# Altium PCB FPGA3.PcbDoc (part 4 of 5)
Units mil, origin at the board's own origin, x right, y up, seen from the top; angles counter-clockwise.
Board outline 4000 x 2750 mil, 12 copper layers (Top Layer, Plane1, MidLayer1, Plane2, MidLayer2, Plane3, Plane4, MidLayer 3, Plane5, MidLayer 4, Plane6, Bottom Layer), stack 57.29 mil thick; 420 components, 368 nets, 1889 pads, 1236 vias.
Unrouted connection lines stored in the file: 1.
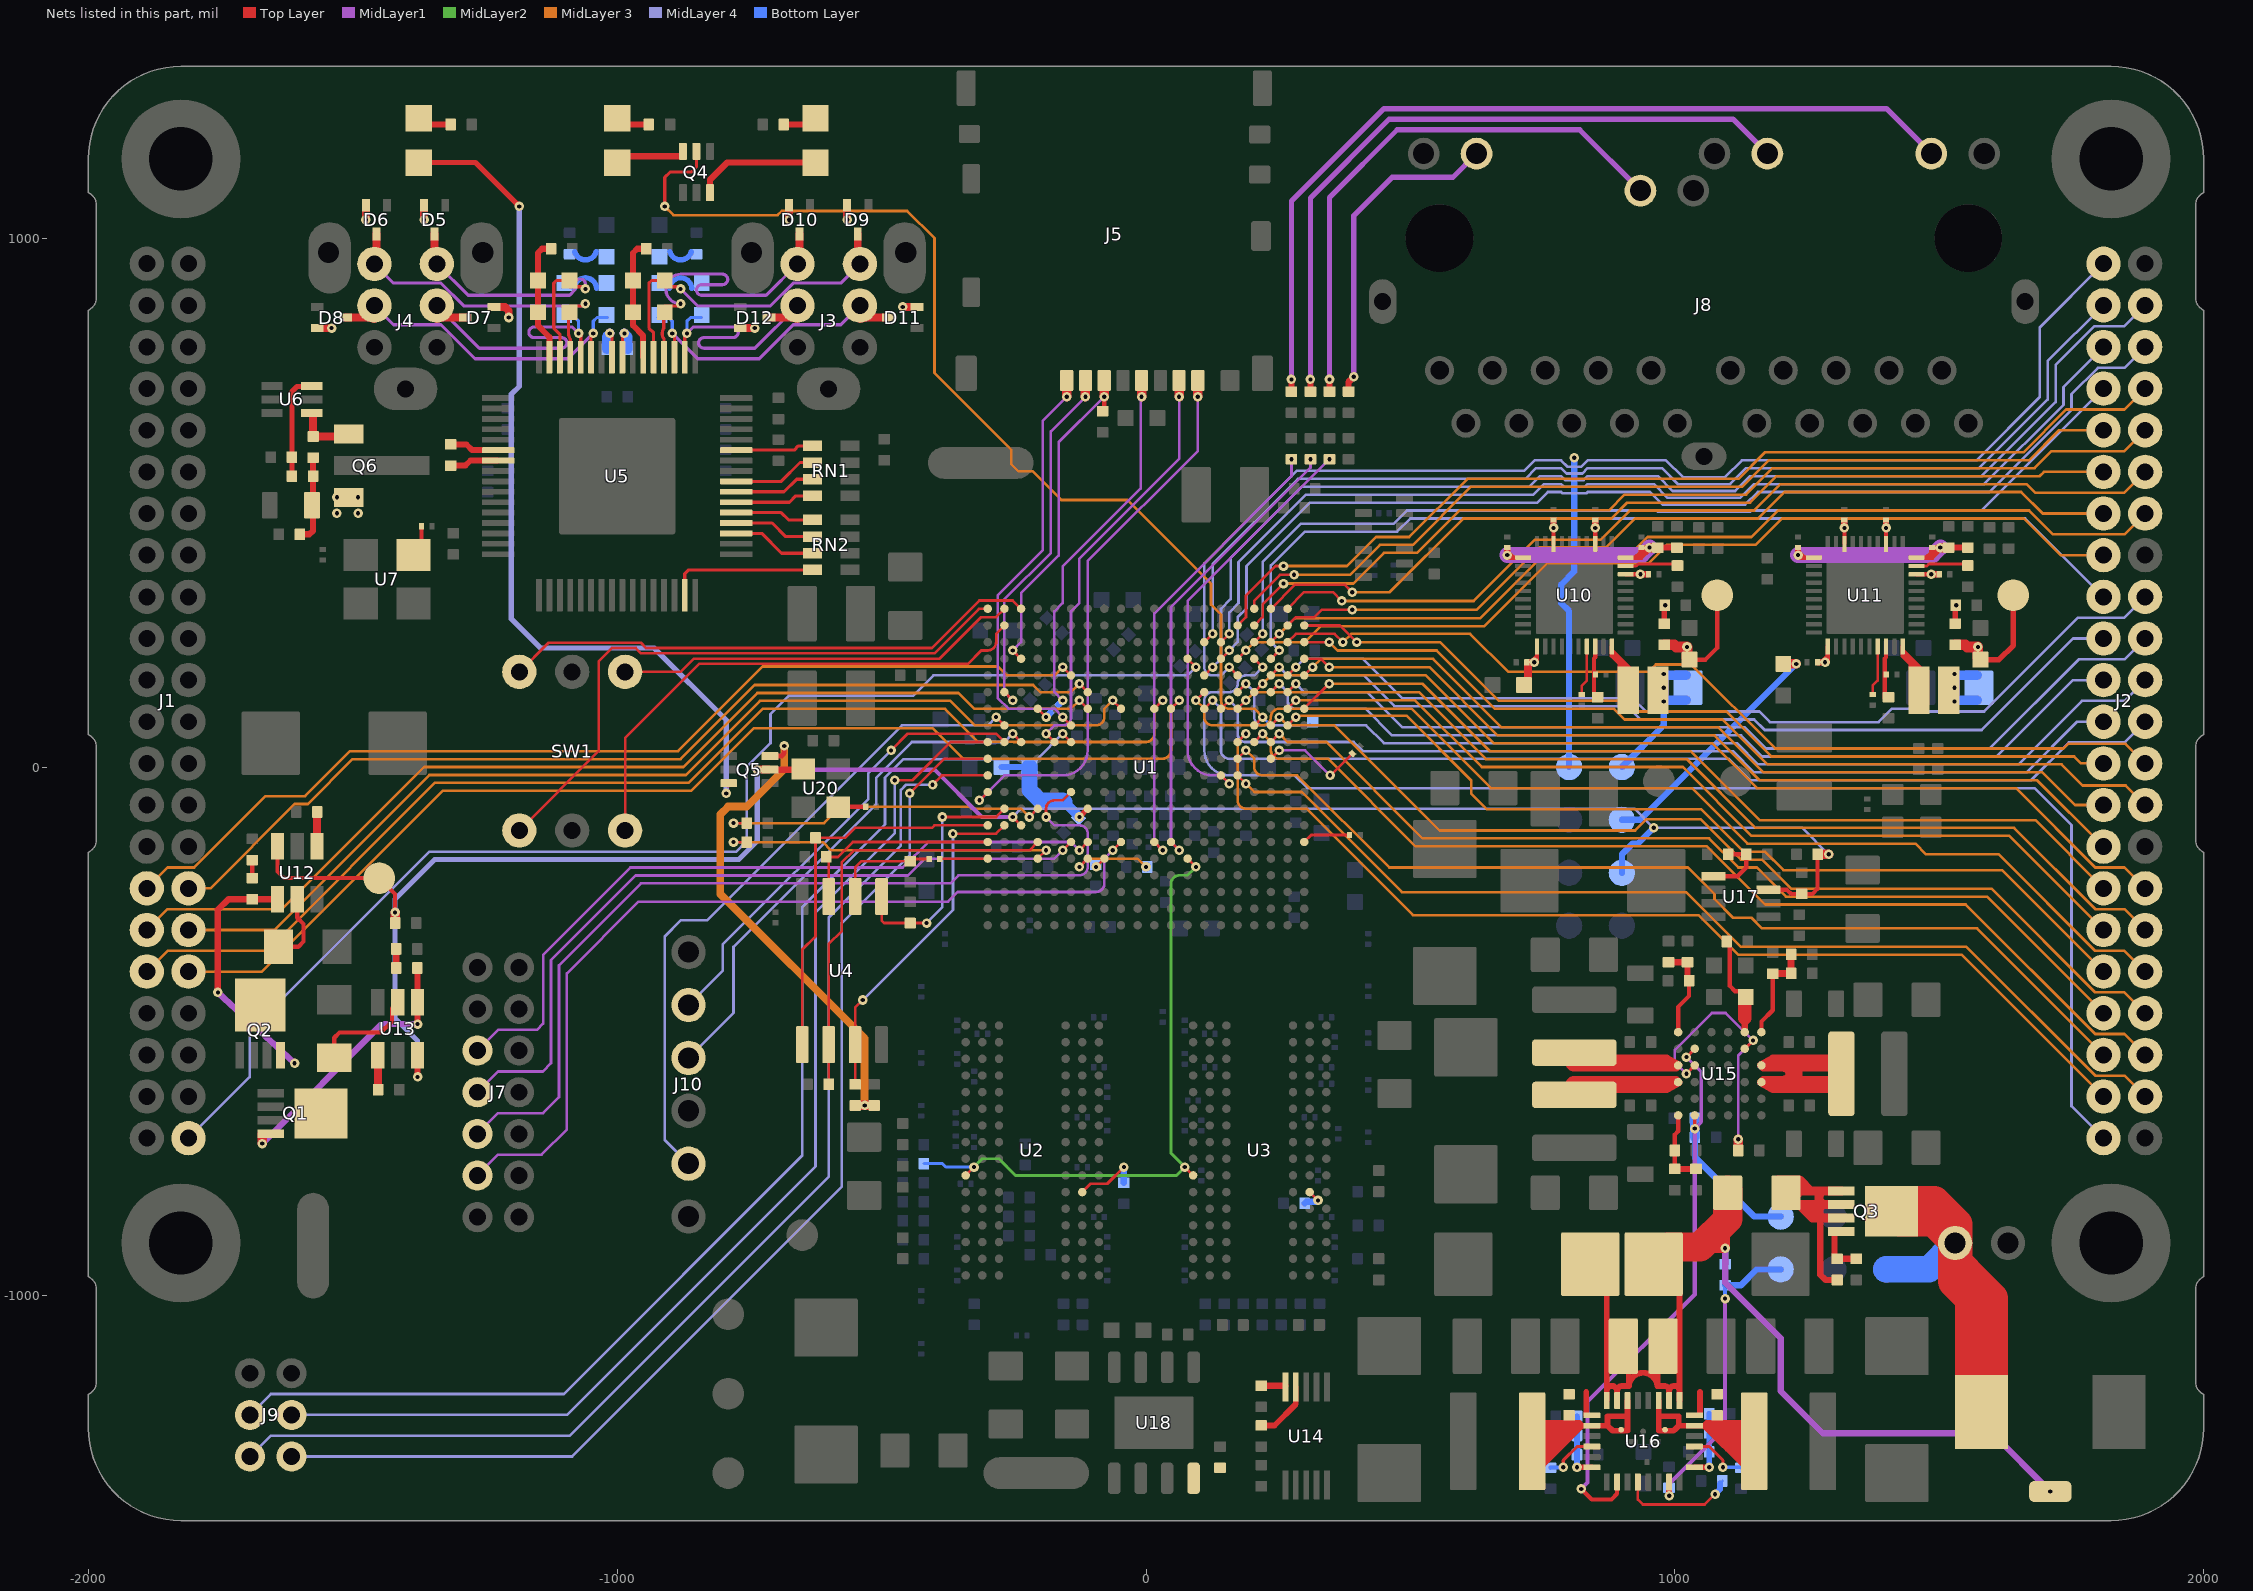
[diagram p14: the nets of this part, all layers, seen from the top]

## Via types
v1: diameter 18, hole 8, Top Layer to Bottom Layer, tented both sides, 1236 vias

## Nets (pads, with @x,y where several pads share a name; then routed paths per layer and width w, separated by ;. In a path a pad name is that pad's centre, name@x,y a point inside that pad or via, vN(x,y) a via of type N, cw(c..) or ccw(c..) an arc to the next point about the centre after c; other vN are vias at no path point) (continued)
IO1-27: J1.31 U1.G15 | length 1879.1
  Top Layer w5: v1(-125.98,157.48) U1.G15@-110.24,141.73
  MidLayer 3 w5: J1.31@-1809.96,-230 J1.31@-1810.63,-229.33 -1769.33,-229.33 -1610,-70 -1585,-70 -1500,15 -880,15 -740,155 -213.27,155 -200,141.73 -141.73,141.73 v1(-125.98,157.48)
IO1-28: J1.32 U1.F16 | length 1941.3
  Top Layer w5: v1(-157.48,188.98) U1.F16@-141.73,173.23
  MidLayer 3 w5: J1.32@-1889.37,-229.33 -1850,-189.96 -1799.96,-189.96 -1665,-55 -1590,-55 -1505,30 -885,30 -725,190 -280,190 -263.23,173.23 -173.23,173.23 v1(-157.48,188.98)
IO1-29: J1.33 U1.J14 | length 1999.7
  Top Layer w5: v1(-62.99,125.98) U1.J14@-47.24,110.24
  MidLayer 3 w5: J1.33@-1810.63,-308.07 -1648.07,-308.07 -1355,-15 -870,-15 -730,125 -370,125 -323.74,78.74 -94.33,78.74 ccw(c-94.49,94.49) -78.74,94.49 -78.74,110.24 v1(-62.99,125.98)
IO1-30: J1.34 U1.G14 | length 1990.1
  Top Layer w5: v1(-125.98,125.98) U1.G14@-110.24,110.24
  MidLayer 3 w5: J1.34@-1889.37,-308.07 -1850,-268.7 -1633.7,-268.7 -1365,0 -875,0 -735,140 -354.76,140 -325,110.24 -141.73,110.24 v1(-125.98,125.98)
IO1-31: J1.35 U1.M14 | length 2204.3
  Top Layer w5: U1.M14@47.24,110.24 v1(62.99,125.98)
  MidLayer 3 w5: J1.35@-1810.63,-386.81 -1671.81,-386.81 -1330,-45 -860,-45 -742,73 -403,73 -345.75,15.75 -265,15.75 31.66,15.75 ccw(c31.5,31.5) 47.24,31.5 47.24,110.24 v1(62.99,125.98)
IO1-32: J1.36 U1.L14 | length 2237.6
  Top Layer w5: U1.L14@15.75,110.24 v1(31.5,125.98)
  MidLayer 3 w5: J1.36@-1889.37,-386.81 -1850,-347.44 -1662.44,-347.44 -1345,-30 -865,-30 -725,110 -380,110 -317.49,47.49 -250,47.49 ; -250,47.24 0.16,47.24 ccw(c0,62.99) 15.75,62.99 15.75,110.24 v1(31.5,125.98)
IO1-33: J1.43 U1.N17 | length 2461.2
  Top Layer w5: U1.N17@78.74,204.72 v1(94.49,188.98)
  MidLayer 4 w5: J1.43@-1810.63,-701.77 -1695,-586.14 -1695,-500 -1355,-160 -774.67,-160 -755,-140.33 -755,0 -710,45 -710,100 -675,135 -440,135 -401.77,173.23 78.74,173.23 v1(94.49,188.98)
IO2-0: J2.2 U1.T16 | length 2330
  Top Layer w5: v1(157.48,188.98) U1.T16@173.23,173.23
  MidLayer 4 w5: v1(157.48,188.98) 141.73,173.23 125.98,173.23 cw(c125.98,188.98) 110.24,188.98 110.24,385.24 285,560 715,560 735,580 785,580 797.5,567.5 822.5,567.5 835,580 983,580 1015,548 1095,548 1127,580 1570,580 1690,700 1690,831.14 J2.2@1810.63,951.77
IO2-1: J2.3 U1.P16 | length 2240.2
  Top Layer w5: U1.P16@110.24,173.23 v1(125.98,188.98)
  MidLayer 4 w5: v1(125.98,188.98) 141.73,204.72 141.73,299.21 160,317.48 160,395 295,530 725,530 745,550 785,550 792.5,542.5 827.5,542.5 835,550 968,550 996,522 1114,522 1142,550 1580,550 1720,690 1720,760 1793.66,833.66 1850,833.66 J2.3@1889.37,873.03
IO2-2: J2.4 U1.P18 | length 2116.8
  Top Layer w5: U1.P18@110.24,236.22 v1(125.98,251.97)
  MidLayer 4 w5: v1(125.98,251.97) 125.98,383.48 287.5,545 717.5,545 737.5,565 785,565 795,555 825,555 835,565 975.5,565 1005.5,535 1104.5,535 1134.5,565 1575,565 1705,695 1705,767.4 J2.4@1810.63,873.03
IO2-3: J2.5 U1.R17 | length 2105.8
  Top Layer w5: U1.R17@141.73,204.72 v1(157.48,220.47)
  MidLayer 4 w5: v1(157.48,220.47) 173.23,236.22 173.23,283.23 190,300 190,380 310,500 740,500 760,520 785,520 787.5,517.5 832.5,517.5 835,520 953,520 977,496 1133,496 1157,520 1595,520 1750,675 1750,705 1799.92,754.92 1850,754.92 J2.5@1889.37,794.29
IO2-4: J2.6 U1.R18 | length 2025.9
  Top Layer w5: U1.R18@141.73,236.22 v1(157.48,251.97)
  MidLayer 4 w5: v1(157.48,251.97) 157.48,292.48 175,310 175,387.5 302.5,515 732.5,515 752.5,535 785,535 790,530 830,530 835,535 960.5,535 986.5,509 1123.5,509 1149.5,535 1585,535 1735,685 1735,718.66 J2.6@1810.63,794.29 J2.6@1799.29,794.29
IO2-5: J2.7 U1.T19 | length 1925.4
  Top Layer w5: U1.T19@173.23,267.72 188.98,283.46 188.98,323.98 245,380 v1(260,380)
  MidLayer 3 w5: v1(260,380) 380,380 435,435 497.5,435 607.5,545 1120,545 1170,595 1658.82,595 1740,676.18 1850,676.18 J2.7@1889.37,715.55
IO2-6: J2.8 U1.U18 | length 1885.8
  Top Layer w5: U1.U18@204.72,236.22 v1(220.47,251.97)
  MidLayer 4 w5: v1(220.47,251.97) 220.47,387.97 292.5,460 468.33,460 493.33,485 965.5,485 967.5,483 1142.5,483 1144.5,485 1580.08,485 J2.8@1810.63,715.55
IO2-7: J2.9 U1.U19 | length 1851.6
  Top Layer w5: U1.U19@204.72,267.72 220.47,283.46 220.47,307.47 v1(260,347)
  MidLayer 3 w5: v1(260,347) 392,347 450,405 512.5,405 593,485.5 875.5,485.5 905,515 1135,515 1185,565 1680,565 1712.44,597.44 1850,597.44 J2.9@1889.37,636.81
IO2-8: J2.10 U1.U20 | length 1757.2
  Top Layer w5: U1.U20@204.72,299.21 204.72,314.72 253.5,363.5 v1(280,363.5)
  MidLayer 3 w5: v1(280,363.5) 386,363.5 442.5,420 505,420 615,530 1127.5,530 1177.5,580 1670,580 1726.81,636.81 J2.10@1810.63,636.81 J2.10@1808.95,635.13
IO2-9: J2.11 U1.W20 | length 1756.2
  Top Layer w5: U1.W20@267.72,299.21 299.16,330.66 353.34,330.66 v1(370,314)
  MidLayer 3 w5: v1(370,314) 619.5,314 735.5,430 860,430 915,485 1150,485 1200,535 1665,535 1681.3,518.7 1850,518.7 J2.11@1889.37,558.07
IO2-10: J2.12 U1.V20 | length 1693.6
  Top Layer w5: U1.V20@236.22,299.21 282.01,345 375.5,345 v1(390,330.5)
  MidLayer 3 w5: v1(390,330.5) 460.5,330.5 600,470 880,470 910,500 1142.5,500 1192.5,550 1690,550 1698.07,558.07 J2.12@1810.63,558.07
IO2-11: J2.13 U1.V18 | length 1791.2
  Top Layer w5: U1.V18@236.22,236.22 v1(251.97,251.97)
  MidLayer 3 w5: v1(251.97,251.97) 281,281 631.5,281 750.5,400 913.67,400 948.67,435 1145,435 1195,485 1670,485 1715.04,439.96 1850,439.96 J2.13@1889.37,479.33
IO2-12: J2.14 U1.W19 | length 1664.3
  Top Layer w5: U1.W19@267.72,267.72 283.46,283.46 318.46,283.46 332.5,297.5 v1(390,297.5)
  MidLayer 3 w5: v1(390,297.5) 625.5,297.5 743,415 870,415 925,470 1157.5,470 1207.5,520 1655,520 1695.67,479.33 J2.14@1810.63,479.33
IO2-13: J2.16 U1.T17 | length 1776
  Top Layer w5: U1.T17@173.23,204.72 v1(188.98,220.47)
  MidLayer 3 w5: v1(188.98,220.47) 204.72,236.22 300.24,236.22 330.02,266 639,266 758,385 950,385 985,420 1152.5,420 1202.5,470 1660,470 1729.41,400.59 J2.16@1810.63,400.59
IO2-14: J2.17 U1.W16 | length 1786.5
  Top Layer w5: U1.W16@267.72,173.23 v1(283.46,188.98)
  MidLayer 4 w5: v1(283.46,188.98) 299.21,204.72 410.28,204.72 485,130 920,130 945,105 1160,105 1180,85 1385,85 1410,110 1450,110 1455,105 1585,105 1762.48,282.48 1850,282.48 J2.17@1889.37,321.85
IO2-15: J2.18 U1.V17 | length 1862
  Top Layer w5: U1.V17@236.22,204.72 v1(251.97,220.47)
  MidLayer 4 w5: v1(251.97,220.47) 236.22,236.22 236.22,380.99 300.23,445 475,445 500,470 1662.48,470 J2.18@1810.63,321.85
IO2-16: J2.19 U1.W15 | length 1765.1
  Top Layer w5: U1.W15@267.72,141.73 v1(283.46,157.48)
  MidLayer 4 w5: v1(283.46,157.48) 299.21,141.73 418.27,141.73 485,75 1132.5,75 1172.5,35 1595,35 1763.74,203.74 1850,203.74 J2.19@1889.37,243.11
IO2-17: J2.20 U1.V16 | length 1701.9
  Top Layer w5: U1.V16@236.22,173.23 v1(251.97,188.98)
  MidLayer 4 w5: v1(251.97,188.98) 267.72,173.23 411.77,173.23 470,115 910,115 935,90 1150,90 1170,70 1580,70 1753.11,243.11 J2.20@1810.63,243.11
IO2-18: J2.21 U1.T15 | length 1882
  Top Layer w5: U1.T15@173.23,141.73 v1(188.98,157.48)
  MidLayer 4 w5: v1(188.98,157.48) 204.72,141.73 204.72,94.49 ccw(c220.47,94.49) 220.47,78.74 416.26,78.74 450,45 1117.5,45 1157.5,5 1650,5 1770,125 1850,125 J2.21@1889.37,164.37
IO2-19: J2.22 U1.V15 | length 1709.4
  Top Layer w5: U1.V15@236.22,141.73 v1(251.97,157.48)
  MidLayer 4 w5: v1(251.97,157.48) 267.72,141.73 267.72,125.98 ccw(c283.46,125.98) 283.46,110.24 414.76,110.24 465,60 1125,60 1165,20 1608.13,20 1752.5,164.37 J2.22@1810.63,164.37
IO2-20: J2.23 U1.P14 | length 2024.9
  Top Layer w5: U1.P14@110.24,110.24 v1(125.98,125.98)
  MidLayer 4 w5: 141.73,50.17 141.73,110.24 ; J2.23@1889.37,85.63 1850,46.26 1745,46.26 1673.74,-25 1142.5,-25 1101.75,15.75 157.48,15.75 cw(c157.48,31.5) 141.73,31.5 141.73,110.24 ; 141.73,110.24 v1(125.98,125.98) 141.73,110.24
IO2-21: J2.24 U1.R14 | length 1801.5
  Top Layer w5: U1.R14@141.73,110.24 v1(157.48,125.98)
  MidLayer 4 w5: v1(157.48,125.98) 173.23,110.24 173.23,62.99 ccw(c188.98,62.99) 188.98,47.24 392.76,47.24 410,30 1110,30 1150,-10 1665,-10 1760.63,85.63 J2.24@1810.63,85.63
IO2-22: J2.25 U1.W18 | length 1761.6
  Top Layer w5: U1.W18@267.72,236.22 283.46,251.97 356.71,251.97 v1(372.46,236.22)
  MidLayer 3 w5: v1(372.46,236.22) 388.2,251.97 613.03,251.97 685,180 950,180 964,194 1031,194 1190,35 1735,35 1743.78,43.78 1852.48,43.78 J2.25@1889.37,6.89
IO2-23: J2.26 U1.Y19 | length 1623.7
  Top Layer w5: U1.Y19@299.21,267.72 366.96,267.72 v1(398.46,236.22)
  MidLayer 3 w5: v1@394.21,236.22 v1(398.46,236.22) 556.28,236.22 667.5,125 895,125 915,105 1097.5,105 1182.5,20 1755,20 1768.11,6.89 J2.26@1810.63,6.89
IO2-24: J2.27 U1.Y18 | length 1713.5
  Top Layer w5: U1.Y18@299.21,236.22 v1@342.21,236.22
  MidLayer 3 w5: v1(346.46,236.22) 362.2,220.47 549.53,220.47 660,110 885,110 905,90 1090,90 1175,5 1731.3,5 1771.26,-34.96 1852.48,-34.96 J2.27@1889.37,-71.85
IO2-25: J2.28 U1.Y16 | length 1644.9
  Top Layer w5: U1.Y16@299.21,173.23 v1(314.96,188.98)
  Top Layer w6: J2.28@1806.48,-76 J2.28@1810.63,-71.85
  MidLayer 3 w5: v1(314.96,188.98) 330.71,204.72 542.78,204.72 672.5,75 1082.5,75 1167.5,-10 1695,-10 1756.85,-71.85 J2.28@1810.63,-71.85
IO2-26: J2.30 U1.Y17 | length 1658.6
  Top Layer w5: U1.Y17@299.21,204.72 330.71,204.72 v1(346.46,188.98)
  MidLayer 3 w5: v1(346.46,188.98) 536.02,188.98 665,60 1075,60 1160,-25 1685.04,-25 J2.30@1810.63,-150.59
IO2-27: J2.31 U1.U15 | length 1864.4
  Top Layer w5: U1.U15@204.72,141.73 v1(220.47,157.48)
  MidLayer 3 w5: v1(220.47,157.48) 236.22,173.23 529.27,173.23 657.5,45 1070,45 1155,-40 1645,-40 1794.96,-189.96 1850,-189.96 J2.31@1889.37,-229.33
IO2-28: J2.32 U1.Y14 | length 1691.2
  Top Layer w5: U1.Y14@299.21,110.24 v1(346.46,157.48)
  MidLayer 3 w5: v1(346.46,157.48) 522.52,157.48 650,30 1030,30 1160.5,-100.5 1681.8,-100.5 J2.32@1810.63,-229.33
IO2-29: J2.33 U1.T14 | length 1915.5
  Top Layer w5: U1.T14@173.23,110.24 v1(188.98,125.98)
  MidLayer 3 w5: v1(188.98,125.98) 204.72,141.73 515.77,141.73 642.5,15 1022.5,15 1152.5,-115 1641.26,-115 1794.96,-268.7 1850,-268.7 J2.33@1889.37,-308.07
IO2-30: J2.34 U1.W14 | length 1729.2
  Top Layer w5: U1.W14@267.72,110.24 v1(283.46,125.98)
  MidLayer 3 w5: v1(283.46,125.98) 509.02,125.98 635,0 1015,0 1145,-130 1632.56,-130 J2.34@1810.63,-308.07
IO2-31: J2.35 U1.P15 | length 2072.3
  Top Layer w5: v1(94.49,125.98) U1.P15@110.24,141.73
  MidLayer 3 w5: v1(94.49,125.98) 110.24,110.23 110.24,94.49 ccw(c125.98,94.49) 125.98,78.74 220.47,78.74 ccw(c220.47,94.49) 236.22,94.49 cw(c251.97,94.49) 251.97,110.24 502.26,110.24 652.5,-40 1032.5,-40 1137.5,-145 1455,-145 1475,-165 1612.52,-165 1794.96,-347.44 1850,-347.44 J2.35@1889.37,-386.81
IO2-32: J2.36 U1.W13 | length 1765.5
  Top Layer w5: U1.W13@267.72,78.74 v1(283.46,94.49)
  MidLayer 3 w5: v1(283.46,94.49) 285.95,96.98 292.87,96.98 ; 292.89,97 493,97 615,-25 615,-50 645,-80 1050,-80 1130,-160 1170,-160 1205,-195 1618.82,-195 J2.36@1810.63,-386.81
IO2-33: J2.37 U1.V13 | length 1909.5
  Top Layer w5: U1.V13@236.22,78.74 v1(251.97,94.49)
  MidLayer 3 w5: v1(251.97,94.49) 267.72,78.74 356.26,78.74 555,-120 925,-120 946.5,-98.5 1048.5,-98.5 1125,-175 1165,-175 1220,-230 1598.78,-230 1794.96,-426.18 1850,-426.18 J2.37@1889.37,-465.55
IO2-34: J2.38 U1.V12 | length 1799.9
  Top Layer w5: U1.V12@236.22,47.24 v1(251.97,62.99)
  MidLayer 3 w5: v1(251.97,62.99) 267.72,47.24 340.92,47.24 523.17,-135 1065,-135 1120,-190 1155,-190 1210,-245 1590.08,-245 J2.38@1810.63,-465.55
IO2-35: J2.39 U1.U12 | length 1954.6
  Top Layer w5: U1.U12@204.72,47.24 v1(220.47,62.99)
  MidLayer 3 w5: v1(220.47,62.99) 236.22,47.24 236.22,31.34 ; 236.22,31.5 ccw(c251.97,31.5) 236.22,31.34 ; J2.39@1889.37,-544.29 1850,-504.92 1794.96,-504.92 1550.04,-260 1170.54,-260 1060.54,-150 510,-150 344.25,15.75 251.97,15.75 cw(c251.97,31.5) 236.22,31.34
IO2-36: J2.40 U1.T11 | length 1900
  Top Layer w5: U1.T11@173.23,15.75 v1(188.98,31.5)
  MidLayer 3 w5: v1(188.98,31.5) 204.73,15.75 204.73,-0.16 ccw(c220.47,0) 220.47,-15.75 251.97,-15.75 285.75,-15.75 460,-190 1025,-190 1075,-240 1075,-250 1110,-285 1145,-285 1165,-305 1571.34,-305 J2.40@1810.63,-544.29
IO2-37: J2.41 U1.T10 | length 1967.7
  Top Layer w5: U1.T10@173.23,-15.75 v1(188.98,-31.5)
  MidLayer 3 w5: v1(188.98,-31.5) 204.73,-47.24 251.97,-47.24 294.74,-47.24 484,-236.5 1021.5,-236.5 1125,-340 1551.3,-340 1794.96,-583.66 1850,-583.66 J2.41@1889.37,-623.03
IO2-38: J2.42 U1.T12 | length 2026.6
  Top Layer w5: U1.T12@173.23,47.24 v1(188.98,62.99)
  MidLayer 3 w5: v1(188.98,62.99) 173.23,47.24 173.23,-63.15 ccw(c188.98,-62.99) 188.98,-78.74 251.97,-78.74 303.74,-78.74 505,-280 1045,-280 1120,-355 1542.6,-355 J2.42@1810.63,-623.03
IO2-39: J2.44 U1.U17 | length 2583.1
  Top Layer w5: U1.U17@204.72,204.72 v1(220.47,188.98)
  MidLayer 4 w5: v1(220.47,188.98) 204.72,173.23 188.98,173.23 ccw(c188.98,157.48) 173.23,157.48 cw(c157.48,157.48) 157.48,141.73 125.98,141.73 ccw(c125.98,125.98) 110.24,125.98 110.24,31.5 ccw(c157.48,31.5) 157.48,-15.75 280.75,-15.75 305,-40 1680,-40 1750,-110 1750,-641.14 J2.44@1810.63,-701.77
MIO6_8: R6.1 U1.A5 | length 91.1
  Top Layer w5: R6.1@-390,-174 -389.23,-173.23 U1.A5@-299.21,-173.23
MIO7_8: R84.2 U1.D8 | length 627.7
  Top Layer w5: v1(-780,-106) R84.2@-755,-106 ; v1(-220.47,-94.49) U1.D8@-204.72,-78.74
  MidLayer 3 w5: v1(-780,-106) -609,-106 -578,-75 -333.74,-75 -330,-78.74 -236.22,-78.74 v1(-220.47,-94.49)
MIO8_8: R85.2 U1.D5 | length 644.7
  Top Layer w5: v1(-780,-142) R85.2@-755,-142 ; U1.D5@-204.72,-173.23 v1(-188.98,-157.48)
  MidLayer 3 w5: v1(-780,-142) -610.97,-142 -595.48,-157.48 -531.17,-157.48 v1(-188.98,-157.48)
MIO34: J9.3 U1.A12 | length 2183.2
  Top Layer w5: v1(-475,-25) -441.68,-25 -369.44,47.24 U1.A12@-299.21,47.24
  MidLayer 4 w5: J9.3@-1615.63,-1225 -1095,-1225 -625,-755 -625,-275 -475,-125 v1(-475,-25)
MIO35: J9.4 U1.F12 | length 2419.7
  Top Layer w5: v1(-157.48,62.99) U1.F12@-141.73,47.24
  MidLayer 4 w5: J9.4@-1694.37,-1225 -1655,-1185.63 -1100.63,-1185.63 -650,-735 -650,-265 -493.5,-108.5 -493.5,-20.17 -458.34,15 -205.48,15 v1(-157.48,62.99)
MIO36: J9.5 U1.A11 | length 2223.5
  Top Layer w5: v1(-447,-50) -381.25,15.75 U1.A11@-299.21,15.75
  MidLayer 4 w5: J9.5@-1615.63,-1303.74 -1085.24,-1303.74 -575,-793.5 -575,-295 -447,-167 v1(-447,-50)
MIO37: J9.6 U1.A10 | length 2277.4
  Top Layer w5: v1(-403.5,-33.5) -385.75,-15.75 U1.A10@-299.21,-15.75
  MidLayer 4 w5: J9.6@-1694.37,-1303.74 -1655,-1264.37 -1089.37,-1264.37 -600,-775 -600,-285 -463.5,-148.5 -463.5,-43.17 -453.83,-33.5 v1(-403.5,-33.5)
NetC1_2: C1.2 R99.1 R108.2 U15.A1 | length 178.1
  Top Layer w8: U15.A1@1006.26,-501.26 1006.26,-453.74 1027,-433 R99.1@1027,-404
  Top Layer w12: C1.2@988,-369 R108.2@1024,-369 1024,-401 R99.1@1027,-404
NetC2_2: C2.2 R100.2 R106.1 U15.A6 | length 190.3
  Top Layer w8: U15.A6@1163.74,-501.26 1163.74,-481.26 1185,-460 R106.1@1185,-391
  Top Layer w13: R106.1@1185,-391 1185.85,-390.15 C2.2@1219.88,-390.15 R100.2@1219.88,-354.15
NetC3_2: C3.2 R101.1 R107.2 U15.F1 | length 137.6
  Top Layer w8: C3.2@1000,-753.74 R101.1@1000,-725 1000,-695 1006.26,-688.74 U15.F1@1006.26,-658.74
  Top Layer w12: C3.2@1000,-760 R107.2@1040,-760
NetC4_2: C4.2 R81.1 R103.2 U16.9 | length 129.2
  Top Layer w11: U16.9@1037,-1324.21 v1(1065,-1324.21)
  Bottom Layer w11: v1(1065,-1324.21) R103.2@1065,-1259 C4.2@1065,-1223
NetC5_2: C5.2 R97.1 R104.2 U16.28 | length 124.2
  Top Layer w11: v1(815,-1324.21) U16.28@843,-1324.21
  Bottom Layer w11: v1(815,-1324.21) C5.2@815,-1228
NetC6_1: C6.1 R76.1 R113.2 R114.2 | length 118.8
  Bottom Layer w10: -900.95,905.46 cw(c-880,904) -859.05,905.46 ; -900.38,974.92 ccw(c-880,980) R76.1@-859.62,974.92
NetC7_1: C7.1 R77.1 R115.2 R116.2 | length 118.8
  Bottom Layer w10: -1080.95,905.46 cw(c-1060,904) -1039.05,905.46 ; R77.1@-1080.38,974.92 ccw(c-1060,980) -1039.62,974.92
NetC8_1: C8.1 R36.2 | length 34
  Top Layer w8: R36.2@-1690,-210 C8.1@-1690,-176
NetC9_1: C9.1 R37.2 | length 36
  Top Layer w12: R37.2@-1418,-380 C9.1@-1418,-344
NetC10_1: C10.1 U5.54 | length 94.5
  Top Layer w11: C10.1@-1315,610 -1285,610 -1274.21,599.21 U5.54@-1225,599.21
NetC10_2: C10.2 U5.55 | length 92.9
  Top Layer w11: C10.2@-1315,570 -1287,570 -1277.47,579.53 U5.55@-1226,579.53
NetC21_1: C21.1 U18.4
NetC23_1: C23.1 U16.23 | length 44.3
  Top Layer w11: U16.23@832.5,-1225.79 832.5,-1181.5
NetC23_2: C23.2 L2.1 U16.20 U16.24 U16.33 | length 708.7
  Top Layer w11: L2.1@724.97,-1289.56 780.44,-1289.56 ; L2.1@734.97,-1279.56 790.44,-1279.56 ; L2.1@744.97,-1269.56 800.44,-1269.56 ; L2.1@750.3,-1319.69 820.5,-1249.5 ; 755,-1259.53 810.47,-1259.53 ; 800,-1249.5 820.5,-1249.5 ; 800,-1245 800.47,-1245.47 824.53,-1245.47 ; 800,-1240.5 819.56,-1240.5 824.53,-1245.47 ; 910.47,-1227.53 872.53,-1227.53 872.53,-1245.47 ; 910.47,-1220 U16.20@910.47,-1198 910.47,-1255.19 882.38,-1255.19 872.53,-1245.47 ; 820.5,-1249.5 824.53,-1245.47 ; 824.53,-1245.47 U16.24@843,-1245.47 872.53,-1245.47
  Top Layer w20: L2.1@735,-1245 800,-1245 ; L2.1@740.44,-1299.56 760.44,-1299.56
NetC24_1: C24.1 U16.14 | length 44.3
  Top Layer w11: U16.14@1047.5,-1225.79 1047.5,-1181.5
NetC24_2: C24.2 L1.1 U16.13 U16.17 U16.34 | length 686
  Top Layer w11: U16.17@969.53,-1198 969.53,-1227.53 ; 1069.53,-1259.53 L1.1@1125,-1259.53 ; 1079.56,-1269.56 L1.1@1135.03,-1269.56 ; 1079.53,-1245.47 1059.5,-1245.47 1055.47,-1245.47 ; 1080,-1249.5 1059.5,-1249.5 ; 1080,-1240.5 1060.44,-1240.5 1055.47,-1245.47 ; 1089.56,-1279.56 L1.1@1145.03,-1279.56 ; 1099.56,-1289.56 L1.1@1155.03,-1289.56 ; L1.1@1129.7,-1319.69 1059.5,-1249.5 ; 969.53,-1227.53 1007.47,-1227.53 1007.47,-1245.47 ; 969.53,-1227.53 969.53,-1255.19 981.5,-1255.19 997.62,-1255.19 1000.73,-1252.12 1007.47,-1245.47 ; 1007.47,-1245.47 U16.13@1037,-1245.47 1055.47,-1245.47 ; 1055.47,-1245.47 1059.5,-1249.5
  Top Layer w20: 1080,-1245 L1.1@1145,-1245 ; 1119.56,-1299.56 L1.1@1139.56,-1299.56
NetC31_1: C31.1 R109.1 R110.1 U5.47 | length 234.4
  Top Layer w11.5: U5.47@-1127.95,775 -1127.95,812.95 -1150,835 R110.1@-1150,860 R109.1@-1150,920 -1150,972 -1142,980 C31.1@-1125,980
NetC32_1: C32.1 R111.1 R112.1 U5.38 | length 233.3
  Top Layer w11.5: U5.38@-950.79,775 -950.79,815.79 -970,835 R112.1@-970,860 R111.1@-970,920 -970,972 -962,980 C32.1@-945,980
NetC33_1: C33.1 U12.1 | length 66
  Top Layer w8: C33.1@-1567.5,-87.5 C33.1@-1565,-85
  Top Layer w15: U12.1@-1567.5,-150 C33.1@-1567.5,-87.5
NetC34_1: C34.1 U13.1 | length 65.2
  Top Layer w15: U13.1@-1452.5,-545 -1452,-545.5 C34.1@-1452,-610
NetC35_1: C35.1 CB55.1 CB59.1 L13.1 U10.11 U10.40 | length 514.2
  Top Layer w8: v1@683,395.87 695.07,395.87 ; v1@686.54,404.4 695.07,395.87 ; U10.11@713,395.87 695.07,395.87 ; U10.40@907,395.87 937,395.87 951.52,410.39 963.39,410.39 C35.1@968,415 ; 924.93,395.87 935,405.94 935,414 936,415 CB55.1@937,415 ; 929,395.87 943.52,410.39
  Top Layer w10: CB55.1@938,415 v1(952,415)
  Top Layer w12: v1(683,400.87) 683,414 CB59.1@683,410 ; C35.1@968,415 L13.1@1004,415
  Top Layer w18: v1(952,415) C35.1@968,415
  MidLayer1 w30: v1(683,400.87) 937.87,400.87 v1(952,415)
NetC36_1: C36.1 CB53.1 CB57.1 CB61.1 L11.2 U10.3 U10.8 U10.38 | length 165.8
  Top Layer w8: U10.8@770.67,421.14 v1@770.67,451.14 ; U10.3@849.41,421.14 v1@849.41,451.14 ; U10.38@907,364.37 v1(935,364.37)
  Top Layer w10: L11.2@980,271 980,304 v1(982,306)
  Top Layer w12: v1(770.63,452) CB57.1@770.63,466 ; v1(849.37,452) CB61.1@849.37,466 ; v1(935,364.37) CB53.1@949,364.37
NetC37_1: C37.1 CB49.1 U10.28 | length 98.9
  Top Layer w8: C37.1@847.12,130 847.12,205.46 849.37,207.71 U10.28@849.37,228
NetC38_1: C38.1 CB56.1 CB60.1 L14.1 U11.11 U11.40 | length 510.2
  Top Layer w8: v1@1233,395.87 1245.07,395.87 ; v1@1236.54,404.4 1245.07,395.87 ; U11.11@1263,395.87 1245.07,395.87 ; U11.40@1457,395.87 1474.93,395.87 ; CB60.1@1487,415 1486,415 1485,414 1485,405.94 1474.93,395.87 ; 1493.52,410.39 1479,395.87 ; C38.1@1518,415 1513.39,410.39 1501.52,410.39 1487,395.87 1479,395.87 ; 1474.93,395.87 1479,395.87
  Top Layer w10: CB60.1@1488,415 v1(1502,415)
  Top Layer w12: v1(1233,400.87) CB56.1@1233,414 ; C38.1@1518,415 L14.1@1554,415
  Top Layer w18: v1(1502,415) C38.1@1518,415
  MidLayer1 w30: v1(1233,400.87) 1487.87,400.87 v1(1502,415)
NetC39_1: C39.1 CB54.1 CB58.1 CB62.1 L12.2 U11.3 U11.8 U11.38 | length 166.7
  Top Layer w8: U11.8@1320.63,422 v1(1320.63,452) ; U11.3@1399.37,422 v1(1399.37,452) ; U11.38@1457,364.37 v1(1485,364.37) ; CB54.1@1499.37,364.37 CB54.1@1500,365
  Top Layer w10: L12.2@1530,271 1530,304 v1(1532,306)
  Top Layer w12: v1(1320.63,452) CB58.1@1320.63,466 ; v1(1399.37,452) CB62.1@1399.37,466 ; v1(1485,364.37) CB54.1@1499,364.37
NetC40_1: C40.1 CB50.1 U11.28 | length 98.9
  Top Layer w8: C40.1@1397.12,130 1397.12,205.46 1399.37,207.71 U11.28@1399.37,228
NetC57_1: C57.1 CB52.1 CB134.1 CB136.1 L7.2 L12.1 pad.0@1640,325 TP9.1 U11.21 | length 898.3
  Top Layer w8: v1@1280.6,201.54 1289.13,210.07 ; v1@1289.13,198 1289.13,210.07 ; U11.21@1289.13,228 1289.13,210.07
  Top Layer w10: CB134.1@1578,203 1613,203 1640,230 pad.0@1640,325
  Top Layer w12: CB52.1@1271,198 v1(1284.13,198)
  Top Layer w18: CB136.1@1210,195 v1(1229.5,195)
  Top Layer w20: L12.1@1530,231 1549,231 1553,227 v1(1573,227) CB134.1@1573,207
  Bottom Layer w12: TP9.1@900,-100 934.5,-100 v1(1229.5,195)
  Bottom Layer w18: C57.1@1571.5,126.5 1531.5,126.5 v1(1529,124) v1(1529,150) v1(1529,176) 1531.5,173.5 C57.1@1571.5,173.5
NetC58_1: C58.1 CB51.1 CB135.1 CB140.1 L6.2 L11.1 pad.0@1080,325 TP7.1 U10.21 | length 643.5
  Top Layer w8: v1@730.6,201.54 739.13,210.07 ; v1@739.13,198 739.13,210.07 ; U10.21@739.13,228 739.13,210.07 ; CB135.1@1027,203 CB135.1@1028,203 1058,203 1080,225 pad.0@1080,325 pad.0@1080,340
  Top Layer w12: CB140.1@715,155 CB140.1@720,160 ; CB51.1@721,198 v1(734.13,198)
  Top Layer w15: CB140.1@722.5,158 CB51.1@722.5,196
  Top Layer w20: L11.1@980,231 999,231 1003,227 v1(1023,227) 1023,207 CB135.1@1027,203
  Bottom Layer w12: TP7.1@900,0 979,79 v1(979,124)
  Bottom Layer w18: C58.1@1021.5,126.5 981.5,126.5 v1(979,124) v1(979,150) v1(979,176) 981.5,173.5 C58.1@1021.5,173.5
NetC77_1: C77.1 U16.26 | length 102.4
  Top Layer w6: v1(789,-1324.21) 789,-1311 815.16,-1284.84 U16.26@843,-1284.84
  Bottom Layer w8: C77.1@765,-1325 765.39,-1324.61 788.61,-1324.61 v1(789,-1324.21)
NetC78_1: C78.1 U16.11 | length 112.4
  Top Layer w6: U16.11@1037,-1284.84 1064.84,-1284.84 1091,-1311 v1(1091,-1324.21)
  Bottom Layer w6: v1(1091,-1324.21) 1124.21,-1324.21 C78.1@1125,-1325
NetCB108_1: CB108.1 CB117.1 L8.2 U1.G8 | length 242.4
  Top Layer w10: v1(-125.98,-94.49) U1.G8@-110.24,-78.74
  Bottom Layer w12: L8.2@-273.15,0 CB117.1@-220,0
  Bottom Layer w18: -160,-60.47 v1(-125.98,-94.49)
  Bottom Layer w30: CB117.1@-220,0 -220,-43.78 -200.79,-62.99 -157.48,-62.99 -154.18,-66.29
NetCB139_1: CB139.1 R9.1 U15.A5 | length 190.4
  Top Layer w8: R9.1@1104,-329 1104,-414 1114,-424 CB139.1@1129,-424
  Top Layer w12: U15.A5@1132.24,-501.26 1132.24,-460
  Top Layer w26: 1132.24,-475 CB139.1@1132.24,-440
NetD2_1: D2.1 Q5.6 | length 1642.8
  Top Layer w10: D2.1@-1375,1143 -1268,1143 v1(-1185,1060)
  Top Layer w12: Q5.6@-789.56,-32.59 -787.56,-30.59 Q5.6@-782.5,-30.59
  MidLayer 4 w10: v1(-1185,1060) -1185,720 -1200,705 -1200,280 -1145,225 -930,225 -793.5,88.5 v1(-793.5,-50)
NetD2_2: D2.2 R46.1 | length 57
  Top Layer w12: D2.2@-1372,1215 R46.1@-1315,1215
NetD3_1: D3.1 Q4.3 | length 235.9
  Top Layer w12: Q4.3@-824.41,1087.5 -824.41,1110.59 -792,1143 D3.1@-625,1143
NetD3_2: D3.2 R48.1 | length 57
  Top Layer w12: R48.1@-680,1215 D3.2@-623,1215
NetD4_1: D4.1 Q4.6 | length 135.7
  Top Layer w12: D4.1@-1000,1143 -988,1155 -877.59,1155 -875.59,1157 Q4.6@-875.59,1162.5
NetD4_2: D4.2 R47.2 | length 61.2
  Top Layer w12: D4.2@-1000,1227 D4.2@-997,1230 ; D4.2@-997,1215 R47.2@-940,1215
NetJ8_12A: J8.12A R42.1 | length 1055.7
  Top Layer w12: R42.1@347,710 v1(347,733)
  MidLayer1 w10: v1(347,733) 347,1077 475,1205 820,1205 J8.12A@935,1090
NetJ8_12B: J8.12B R40.1 | length 1677.7
  Top Layer w12: R40.1@275,710 v1(275,733)
  MidLayer1 w10: v1(275,733) 275,1070 450,1245 1400,1245 J8.12B@1485,1160
NetJ8_13A: J8.13A R43.2 | length 617.6
  Top Layer w12: R43.2@383,710 383,727.97 v1(393,738)
  MidLayer1 w10: v1(393,738) 393,1043 465,1115 580,1115 J8.13A@625,1160
NetJ8_13B: J8.13B R41.2 | length 1318.6
  Top Layer w12: R41.2@311,710 v1(311,733)
  MidLayer1 w10: v1(311,733) 311,1076 460,1225 1110,1225 J8.13B@1175,1160
NetL3_1: L3.1 U15.C6 U15.D6 | length 431.5
  Top Layer w16: 1203,-592 1167.49,-592 U15.D6@1163.74,-595.75 1184.96,-608 1204,-608 ; 1203,-568 1167.49,-568 U15.C6@1163.74,-564.25 1184.96,-552 1204,-552
  Top Layer w32: 1193,-600 L3.1@1293,-600 ; 1193,-560 L3.1@1293,-560 ; 1205,-600 ccw(c1205,-580) 1205,-560
NetL4_1: L4.1 U15.D1 | length 252.4
  Top Layer w16: 966,-608 985.04,-608 U15.D1@1006.26,-595.75 1002.51,-592 967,-592
  Top Layer w32: L4.1@808.99,-600 977,-600
NetL5_1: L5.1 U15.C1 | length 252.4
  Top Layer w16: 966,-552 985.04,-552 U15.C1@1006.26,-564.25 1002.51,-568 967,-568
  Top Layer w32: L5.1@808.99,-560 977,-560
NetL6_1: L6.1 U10.30 | length 213.9
  Top Layer w8: U10.30@880.87,220.13 L6.1@916.22,184.78 ; U10.30@880.87,228 880.87,210.13 896.01,194.99 896.01,160.99 L6.1@912,145 ; L6.1@902,163 902,197 ; L6.1@908,159 908,193
NetL7_1: L7.1 U11.30 | length 213.9
  Top Layer w8: U11.30@1430.87,220.13 L7.1@1466.22,184.78 ; U11.30@1430.87,228 1430.87,210.13 1446.01,194.99 1446.01,160.99 L7.1@1462,145 ; L7.1@1452,163 1452,197 ; L7.1@1458,159 1458,193
NetL15_1: L15.1 Q3.1 Q3.2 Q3.3 R78.1 | length 745
  Top Layer w12: 1275,-845 1275,-852.8 1275,-960 1285,-970 R78.1@1307,-970
  Top Layer w16.5: L15.1@1194.5,-780.5 1236.39,-780.5 1257.5,-801.61 ; L15.1@1199,-829.5 1236.7,-829.5 1260,-852.8 1284.88,-852.8 ; L15.1@1200,-827.2 Q3.2@1315,-827.2 ; L15.1@1200,-801.61 L15.1@1227.5,-801.61 ; L15.1@1216.39,-780.5 1237.5,-801.61 ; L15.1@1227.5,-817.5 L15.1@1227.5,-802.5 ; L15.1@1227.5,-800.86 L15.1@1227.5,-801.61 ; L15.1@1232.2,-807.2 L15.1@1227.5,-802.5 ; 1251.7,-829.5 1275,-852.8 ; 1285,-852.8 cw(c1285,-840) 1284.88,-852.8 ; 1285.12,-827.21 cw(c1285.12,-814.41) 1285,-827.2 ; 1285.12,-801.61 ccw(c1285.12,-814.41) 1284.99,-827.2 ; Q3.3@1315,-852.8 1284.88,-852.8 ; Q3.1@1315,-801.61 1257.5,-801.61 ; L15.1@1227.5,-802.5 L15.1@1227.5,-801.61 ; L15.1@1227.5,-801.61 1257.5,-801.61 ; 1284.88,-852.8 cw(c1285,-840) 1284.99,-827.21
NetQ1_4: Q1.4 R37.1 U13.4 | length 535.6
  Top Layer w12: v1@-1674,-712.01 Q1.4@-1674,-693.39 ; v1@-1668,-712.01 Q1.4@-1668,-693.39 ; R37.1@-1378,-380 -1377.5,-380.5 U13.4@-1377.5,-445 v1(-1377.5,-486) v1@-1377.5,-488.53
  MidLayer1 w12: v1(-1671,-712.01) -1444.99,-486 v1(-1377.5,-486) v1@-1377.5,-488.53
NetQ1_5: Q1.5 R118.2 U13.5 | length 183.3
  Top Layer w8: R118.2@-1535,-547 -1535,-512 -1525,-502 -1447,-502 -1426,-481 -1426,-456 U13.5@-1425,-455
NetQ2_4: Q2.4 R36.1 U12.4 | length 480.9
  Top Layer w12: v1(-1755,-426.18) -1755,-270 -1735,-250 U12.4@-1642.5,-250 U12.4@-1637.5,-250
  MidLayer1 w12: v1@-1753.85,-427.33 v1(-1755,-426.18) v1(-1610,-560)
NetQ2_5: Q2.5 R117.2 U12.5 | length 136.1
  Top Layer w8: R117.2@-1640,-340 -1603,-340 -1593,-330 -1593,-297 -1605,-285 U12.5@-1605,-250
NetQ3_4: Q3.4 R73.1 R78.2 | length 107.3
  Top Layer w12: R78.2@1302,-930 Q3.4@1302,-880 ; R78.2@1306,-929 R78.2@1307,-930 R73.1@1343,-930 ; Q3.4@1306,-880.64 1308.25,-878.39 Q3.4@1325,-878.39
NetQ5_3: Q5.3 R54.1 R91.1 | length 944.2
  Top Layer w9: Q5.3@-712.36,20.73 -689.27,20.73 -684,26 v1(-684,40)
  Top Layer w18: R91.1@-550,-640 v1(-532,-640) R54.1@-514,-640
  MidLayer 3 w15: v1(-684,40) -684,-4 -755,-75 -790,-75 -805,-90 -805,-240 -532,-513 v1(-532,-640)
NetQ6_1: Q6.1 R56.2 U6.1 | length 116.5
  Top Layer w15: U6.1@-1577.5,669.41 -1575,669.41 R56.2@-1575,625 -1512.5,625 Q6.1@-1507.5,630
NetR1_1: R1.1 U1.V11 | length 197.4
  Top Layer w5: U1.V11@236.22,15.75 v1(251.97,31.5) ; v1@349.25,-15.75 R1.1@390.43,25.43
  Top Layer w8: v1(348,-15.75) v1@349.25,-15.75
  MidLayer1 w5: v1(251.97,31.5) 300.76,31.5 v1(348,-15.75)
NetR2_1: R2.1 U1.Y6 | length 91.3
  Top Layer w5: U1.Y6@299.21,-141.73 312.46,-128.48 R2.1@385,-128.48
NetR3_2: R3.2 U10.27 | length 95
  Top Layer w5: R3.2@824,137 824,154 833.62,163.62 U10.27@833.62,228
NetR4_2: R4.2 U11.27 | length 95
  Top Layer w5: R4.2@1374,137 1374,154 1383.62,163.62 U11.27@1383.62,228
NetR5_2: R5.2 U20.3 | length 52.4
  Top Layer w9: U20.3@-582,-76 -579,-76 -578,-75 R5.2@-530,-75
NetR7_1: R7.1 U7.3 | length 62.3
  Top Layer w8: U7.3@-1390,401 -1370,421 R7.1@-1370,455
NetR33_1: R33.1 U1.G5 | length 161.3
  Top Layer w5: v1(-125.98,-188.98) U1.G5@-110.24,-173.23
  MidLayer 3 w5: v1(-125.98,-188.98) -110.24,-173.23 -15.75,-173.23 v1(0,-188.98)
NetR34_2: R34.2 U1.H5 | length 22.3
  Top Layer w5: v1(-94.49,-188.98) U1.H5@-78.74,-173.23
NetR44_1: R44.1 U3.L8 | length 49.8
  Top Layer w5: U3.L8@309.49,-803.74 v1(325.24,-819.49)
  Bottom Layer w12: R44.1@300,-825 303.05,-821.95 321.15,-821.95 323.61,-819.49 v1(325.24,-819.49)
NetR45_1: R45.1 U2.L8 | length 155.2
  Top Layer w5.49: U2.L8@-120.51,-803.74 -104.76,-787.99 ; -77.5,-787.99 -104.76,-787.99 ; v1(-41.77,-756.5) -73.27,-787.99 -104.76,-787.99
  Bottom Layer w12: R45.1@-42,-786 -41.77,-785.77 v1(-41.77,-756.5)
NetR49_2: R49.2 U1.L6 | length 875.7
  Top Layer w5: U1.L6@15.75,-141.73 v1(31.5,-157.48)
  MidLayer1 w5: v1(31.5,-157.48) 15.75,-141.73 15.75,290.75 275,550 v1(275,582)
NetR50_2: R50.2 U1.M6 | length 877.5
  Top Layer w5: U1.M6@47.24,-141.73 v1(62.99,-157.48)
  MidLayer1 w5: v1(62.99,-157.48) 47.24,-141.73 47.24,302.24 311,566 v1(311,582)
NetR51_2: R51.2 U1.R10 | length 796.2
  Top Layer w5: U1.R10@141.73,-15.75 v1(157.48,-31.5)
  MidLayer1 w5: v1(157.48,-31.5) 141.73,-15.75 125.93,-15.75 cw(c125.93,31.5) 78.69,31.5 78.74,31.55 78.74,313.74 v1(347,582)
NetR65_1: R65.1 U10.39 | length 100.6
  Top Layer w6: U10.39@907,380.12 926.71,380.12 930.45,383.87 999.13,383.87 R65.1@1004,379
NetR66_1: R66.1 U11.39 | length 107
  Top Layer w6: U11.39@1457,380.12 1476.71,380.12 1480.45,383.87 1549.13,383.87 1554,379 1554,380.49 R66.1@1550.49,384
NetR79_1: R79.1 U5.40 | length 75.3
  Top Layer w6: U5.40@-990.16,778.9 -990.16,816 v1(-986.16,820)
  Bottom Layer w18: v1(-986.16,820) -980,813.84 R79.1@-980,790
NetR79_2: R79.2 U5.41 | length 79.2
  Top Layer w6: v1(-1013.84,820) -1009.84,816 U5.41@-1009.84,775
  Bottom Layer w18: R79.2@-1020,790 -1020,813.84 v1(-1013.84,820)
NetR82_1: R82.1 R93.2 U6.3 | length 216.9
  Top Layer w10: R93.2@-1615,550 R82.1@-1615,586 ; -1615,571 -1615,710 -1605.31,719.69 -1578.4,719.69 U6.3@-1577.5,720.59
NetR92_1: R92.1 R102.2 TP5.1 U16.7 | length 585.2
  Top Layer w11: v1(989.21,-1378) U16.7@989.21,-1352
  MidLayer1 w8: v1(989.21,-1378) 989.21,-1355.79 1095,-1250 v1(1095,-1005)
  Bottom Layer w8: v1(1095,-1005) R102.2@1095,-980
  Bottom Layer w12: R102.2@1095,-980 1125,-980 1155,-950 TP5.1@1200,-950
NetR94_1: R94.1 U14.10 | length 45
  Top Layer w12: R94.1@218,-1170 U14.10@263,-1170
NetR95_1: R95.1 U14.9 | length 114.2
  Top Layer w11: R95.1@218,-1245 243,-1245 283.31,-1204.69 U14.9@283.31,-1172.5
NetR96_1: R96.1 U16.4 | length 221.7
  Top Layer w5: U16.4@930.16,-1352 930.16,-1385.16 939.5,-1394.5 1056.5,-1394.5 v1(1076,-1375)
  Bottom Layer w5: R96.1@1085.43,-1354.57 R96.1@1090,-1350
  Bottom Layer w11: v1(1076,-1375) 1085.43,-1365.57 R96.1@1085.43,-1354.57
NetR98_2: R98.2 R105.1 U17.5 | length 127.9
  Top Layer w8: U17.5@1073,-206.61 1118.39,-206.61 1135,-190 R105.1@1135,-165 R98.2@1101,-165
NetRN1_5: RN1.5 U5.27 | length 147.8
  Top Layer w6: U5.27@-775,599.21 -665.28,599.21 -657.24,607.24 RN1.5@-630.5,607.24
NetRN1_6: RN1.6 U5.24 | length 159.2
  Top Layer w6: U5.24@-775,540.16 -689.84,540.16 -654.25,575.75 RN1.6@-630.5,575.75
NetRN1_7: RN1.7 U5.23 | length 154.3
  Top Layer w6: U5.23@-775,520.47 -684.53,520.47 -660.75,544.25 RN1.7@-630.5,544.25
NetRN2_7: RN2.7 U5.19 | length 160
  Top Layer w6: U5.19@-775,441.73 -726.73,441.73 -689.25,404.25 RN2.7@-630.5,404.25
NetRN2_8: RN2.8 U5.15 | length 285
  Top Layer w6: U5.15@-872.05,325 -872.05,365.45 -864.74,372.76 RN2.8@-630.5,372.76
ODT_7: R27.1 U1.N5 U2.K1 U3.K1 | length 1198.4
  Top Layer w5: U2.K1@-340.98,-772.24 v1(-325.24,-756.5) ; v1(73.27,-756.5) U3.K1@89.02,-772.24 ; U1.N5@78.74,-173.23 v1(94.49,-188.98)
  MidLayer2 w5.49: v1(-325.24,-756.5) -309.49,-740.75 -277.99,-740.75 -246.5,-772.24 57.52,-772.24 v1(73.27,-756.5) 47.24,-730.47 47.24,-220.47 cw(c62.99,-220.47) 62.99,-204.72 78.74,-204.72 v1(94.49,-188.98)
  Bottom Layer w5.49: R27.1@-420,-750 -385,-750 -378.5,-756.5 v1(-325.24,-756.5)
OK-1.8V_10: C25.1 R74.2 TP6.1 U15.B2 U15.F2 U16.2 | length 1354.5
  Top Layer w6: v1(1022.01,-548.5) U15.B2@1037.76,-532.76 ; v1(1037.76,-683.74) U15.F2@1037.76,-658.74
  Top Layer w8: v1(823,-1365) 843,-1385 880,-1385 890.79,-1374.21 U16.2@890.79,-1352
  MidLayer1 w6: v1(1022.01,-548.5) 1050,-576.5 1050,-671.5 v1(1037.76,-683.74)
  MidLayer1 w8: v1(823,-1365) 835,-1353 835,-1200 1037.76,-997.24 v1(1037.76,-683.74)
  Bottom Layer w12: C25.1@1038,-700 1038,-738 1150,-850 TP6.1@1200,-850
  Bottom Layer w18: C25.1@1038,-700 R74.2@1038,-664
OK-1V_10: R72.2 U15.B5 U15.C2 | length 516.8
  Top Layer w6: v1(1022.01,-580) U15.C2@1037.76,-564.25 ; U15.B5@1132.24,-532.76 v1(1147.99,-517.01)
  Top Layer w18: R72.2@1120,-725 v1(1120,-704)
  MidLayer1 w5: v1(1022.01,-580) 1000,-557.99 1000,-535 1070,-465 1095.98,-465 v1(1147.99,-517.01) 1120,-545 v1(1120,-704)
OUT50_6: J10.2 U1.B13 | length 1269.1
  Top Layer w5: v1(-283.46,94.49) U1.B13@-267.72,78.74
  MidLayer 4 w5: J10.2@-865,-750 -910,-705 -910,-320 -880,-290 -830,-290 -461.26,78.74 -299.21,78.74 v1(-283.46,94.49)
PC0_3: RN2.6 U5.20 | length 155.1
  Top Layer w6: U5.20@-775,461.42 -706.93,461.42 -681.26,435.75 RN2.6@-630.5,435.75
PC1_3: RN2.5 U5.21 | length 150.2
  Top Layer w6: U5.21@-775,481.1 -689.88,481.1 -676.02,467.24 RN2.5@-630.5,467.24
PC2_3: RN1.8 U5.22 | length 149.5
  Top Layer w6: U5.22@-775,500.79 -674.21,500.79 -662.24,512.76 RN1.8@-630.5,512.76
PGOOD: pad.0@-1450,-210 Q5.2 R61.2 R64.2 R80.1 TP11.1 U1.C7 U12.3 U13.3 U17.3 U20.1 | length 4109.4
  Top Layer w5: v1(-251.97,-94.49) U1.C7@-236.22,-110.24
  Top Layer w6: U20.1@-649,-5 U20.1@-648,-4
  Top Layer w8: U12.3@-1642.5,-150 -1642.5,-197.5 -1630,-210 pad.0@-1450,-210 -1420,-240 v1(-1420,-275) ; U13.3@-1380,-523.91 U13.3@-1377.5,-523.91 ; U17.3@1177,-232.2 1212.2,-232.2 1220,-240 R80.1@1240,-240 1260,-240 1270,-230 R64.2@1270,-175
  Top Layer w12: v1(-1377.5,-586) U13.3@-1377.5,-545 ; Q5.2@-711,-5 -682,-5 U20.1@-649,-5
  Top Layer w15: v1(-735,-5) Q5.2@-714,-5
  Top Layer w18: R61.2@-1420,-295 v1(-1420,-275) ; R64.2@1270,-165 v1(1291,-165)
  MidLayer1 w8: v1(-735,-5) -400,-5 -310.51,-94.49 v1(-251.97,-94.49)
  MidLayer 4 w5: v1(-251.97,-94.49) -236.22,-78.74 923.74,-78.74 v1(960,-115) 1241,-115 v1(1291,-165)
  MidLayer 4 w10: v1(-1377.5,-586) -1377.5,-517.5 -1420,-475 v1(-1420,-275) -1420,-250 -1345,-175 -770,-175 -735,-140 v1(-735,-5)
  Bottom Layer w12: TP11.1@900,-200 900,-165 920,-145 930,-145 v1(960,-115)
PUD-C/LED_4: Q4.5 R60.1 R60A.1 U1.U13 | length 2094.2
  Top Layer w5: U1.U13@204.72,78.74 v1(220.47,94.49)
  Top Layer w6: v1(-910,1060) -910,1115 -900,1125 -860,1125 -850,1135 Q4.5@-850,1164
  MidLayer 3 w5: v1(-910,1060) -893.5,1043.5 -696.5,1043.5 -688.5,1051.5 -451.5,1051.5 -400,1000 -400,745 -255,600 -255,573.17 -240.83,559 -214,559 -160,505 -35,505 123,347 123,307 141.73,288.27 141.73,125.93 ccw(c157.48,125.98) 157.48,110.24 204.73,110.24 v1(220.47,94.49)
  Bottom Layer w5: v1(220.47,94.49) 236.22,78.74 308.74,78.74 R60A.1@310,80
PWR_10: D1.1 J6.1 Q3.5 TP1.1 TP2.1 | length 1207.5
  Top Layer w65: Q3.5@1410,-840 1425,-855 1490,-855 J6.1@1530,-895 ; Q3.5@1425,-825 1490,-825 1530,-865 J6.1@1530,-895 ; 1537.4,-944.9 1562.5,-970 ; D1.1@1562.5,-1157.5 1562.5,-1005 ; 1582.5,-1025 1562.5,-1005 ; D1.1@1597.5,-1192.5 1597.5,-1005 1562.5,-970 ; J6.1@1530,-895 J6.1@1530,-900 1530,-972.5 1562.5,-1005 ; 1562.5,-1005 1562.5,-970
  Bottom Layer w50: TP1.1@1400,-950 1480,-950 J6.1@1530,-900 1480,-850 TP2.1@1400,-850
QSPI-/CS_8: R86.2 U1.A7 U4.1 | length 737
  Top Layer w5: U4.1@-650,-525 -650,-345 -625,-320 R86.2@-625,-134 -569,-134 -550,-115 -405,-115 -400.24,-110.24 U1.A7@-299.21,-110.24
QSPI-CLK_8: R6.2 R88.2 U4.6 | length 199
  Top Layer w5: U4.6@-550,-245 -550,-190 -538,-178 R88.2@-446,-178 ; R88.2@-450,-174 R6.2@-415,-174
QSPI-D0_8: R89.2 U1.B8 U4.5 | length 468.8
  Top Layer w5: U4.5@-500,-245 -500,-290 -495,-295 R89.2@-446,-295 v1(-415,-295) ; v1(-385,-94.49) -283.46,-94.49 U1.B8@-267.72,-78.74
  MidLayer 4 w5: v1(-415,-295) -385,-265 v1(-385,-94.49)
QSPI-D1_8: R90.2 U1.D6 U4.2 | length 816.5
  Top Layer w5: R90.2@-600,-600 U4.2@-600,-525 -600,-335 -575,-310 -575,-180 -552.48,-157.48 -220.47,-157.48 U1.D6@-204.72,-141.73
QSPI-D2_8: R91.2 U1.B7 U4.3 | length 654.5
  Top Layer w5: R91.2@-550,-600 U4.3@-550,-525 -550,-455 v1(-535.51,-440.51) ; v1(-365,-125.98) -283.46,-125.98 U1.B7@-267.72,-110.24
  MidLayer 4 w5: v1(-535.51,-440.51) -365,-270 v1(-365,-125.98)
QSPI-D3_8: R87.2 U1.A6 U4.7 | length 377.5
  Top Layer w5: R87.2@-605,-170 -582.5,-170 -554.23,-141.73 U1.A6@-304.21,-141.73 ; U4.7@-600,-245 R87.2@-600,-180
RxD1_6: J10.4 U1.C12 | length 991.7
  Top Layer w5: v1(-251.97,62.99) U1.C12@-236.22,47.24
  MidLayer 4 w5: J10.4@-865,-550 -780,-465 -780,-340 -510,-70 -510,-20 -442.76,47.24 -267.72,47.24 v1(-251.97,62.99)
SD-CLK#_6: J5.5 R8.2 | length 690.7
  Top Layer w18: v1(-8.27,700) J5.5@-8.27,730.83
  MidLayer1 w5: v1(-157.48,125.98) -173.23,141.73 -173.23,294.25 -157.48,310 -157.48,379.18 -10,526.67 -10,698.27 v1(-8.27,700)
  Bottom Layer w12: R8.2@-165.26,118.21 v1(-157.48,125.98)
SD-CLK_6: R8.1 U1.D14 | length 33.3
  Top Layer w5: U1.D14@-204.72,110.24 v1(-188.98,94.49)
  Bottom Layer w12: v1(-188.98,94.49) R8.1@-181.2,102.27
SD-CMD_6: J5.3 R67.1 U1.C17 | length 634.6
  Top Layer w5: v1(-251.97,220.47) U1.C17@-236.22,204.72
  Top Layer w8: R67.1@-80,670 -79.13,670.87 v1(-79.13,700)
  Top Layer w18: v1(-79.13,700) J5.3@-79.13,730.83
  MidLayer1 w5: v1(-251.97,220.47) -236.22,236.22 -236.22,328.78 -165,400 -165,614.13 v1(-79.13,700)
SD-D0_6: J5.7 U1.E12 | length 806
  Top Layer w5: v1(-188.98,62.99) U1.E12@-173.23,47.24
  Top Layer w18: v1(62.6,700) J5.7@62.6,730.83
  MidLayer1 w5: v1(-188.98,62.99) -173.23,78.74 -157.48,78.74 ccw(c-157.48,94.49) -141.73,94.49 -141.73,294.25 -125.98,310 -125.98,394.02 62.6,582.6 v1(62.6,700)
SD-D1_6: J5.8 U1.A9 | length 1059.1
  Top Layer w5: v1(-314.96,-62.99) U1.A9@-299.21,-47.24
  Top Layer w18: v1(98.03,700) J5.8@98.03,730.83
  MidLayer1 w5: v1(-314.96,-62.99) -267.72,-15.75 -157.48,-15.75 ccw(c-157.48,31.5) -110.24,31.5 -110.24,389.76 98.03,598.03 v1(98.03,700)
SD-D2_6: J5.1 U1.F13 | length 814.2
  Top Layer w5: v1(-157.48,94.49) U1.F13@-141.73,78.74
  Top Layer w18: v1(-150,700) J5.1@-150,730.83
  MidLayer1 w5: v1(-157.48,94.49) -173.23,110.24 -260.24,110.24 -280,130 -280,325 -195,410 -195,655 v1(-150,700)
SD-D3_6: J5.2 U1.B15 | length 697.1
  Top Layer w5: U1.B15@-267.72,141.73 v1(-251.97,125.98)
  Top Layer w18: v1(-114.57,700) J5.2@-114.57,730.83
  MidLayer1 w5: v1(-251.97,125.98) -267.72,141.73 -267.72,317.28 -180,405 -180,634.57 v1(-114.57,700)
SEL1_4: SW1.1 U1.A20 | length 1167.3
  Top Layer w5: SW1.1@-1185,-120 -1035,30 -1035,200 -1010,225 -965,225 -955,215 -400,215 -315.79,299.21 U1.A20@-299.21,299.21
SEL2_4: SW1.4 U1.B20 | length 766.7
  Top Layer w5: SW1.4@-985,180 -880,180 -855,205 -390,205 -311.54,283.46 -283.47,283.46 U1.B20@-267.72,299.21
SEL4_4: SW1.3 U1.B19 | length 992.1
  Top Layer w5: SW1.3@-985,-120 -985,55 -845,195 -337.01,195 -311.54,220.47 -299.21,220.47 ccw(c-299.21,236.22) -283.46,236.22 -283.47,251.97 U1.B19@-267.72,267.72
SEL8_4: SW1.6 U1.C20 | length 1019.5
  Top Layer w5: SW1.6@-1185,180 -1130,235 -955,235 -945,225 -405,225 -315,315 -252.01,315 U1.C20@-236.22,299.21
TCK_8: J7.6 U1.F9 | length 1747.5
  Top Layer w5: v1(-188.98,-94.49) -188.98,-78.74 cw(c-173.23,-78.74) -173.23,-62.99 -157.48,-62.99 U1.F9@-141.73,-47.24
  MidLayer1 w5: J7.6@-1264.37,-693.74 -1225,-654.37 -1140,-654.37 -1110,-624.37 -1110,-375 -955,-220 -370,-220 -354.72,-204.72 -125.98,-204.72 ccw(c-125.98,-188.98) -110.24,-188.98 -110.24,-125.98 ccw(c-125.98,-125.98) -125.98,-110.24 -173.23,-110.24 v1(-188.98,-94.49)
TDI_8: J7.10 U1.G6 | length 1406.8
  Top Layer w5: v1(-125.98,-157.48) U1.G6@-110.24,-141.73
  MidLayer1 w5: J7.10@-1264.37,-536.26 -1225,-496.89 -1151.89,-496.89 -1140,-485 -1140,-355 -975,-190 -460,-190 -411.68,-141.68 -141.78,-141.68 v1(-125.98,-157.48)
TDO_8: J7.8 U1.F6 | length 1432.9
  Top Layer w5: v1(-157.48,-157.48) U1.F6@-141.73,-141.73
  MidLayer1 w5: J7.8@-1264.37,-615 -1225,-575.63 -1140.63,-575.63 -1125,-560 -1125,-365 -965,-205 -450,-205 -418.23,-173.23 -173.23,-173.23 v1(-157.48,-157.48)
TMS_8: J7.4 U1.J6 | length 1681.3
  Top Layer w5: v1(-62.99,-157.48) U1.J6@-47.24,-141.73
  MidLayer1 w5: J7.4@-1264.37,-772.48 -1225,-733.11 -1143.11,-733.11 -1095,-685 -1095,-390 -959.5,-254.5 -374.5,-254.5 -356.22,-236.22 -94.49,-236.22 ccw(c-94.49,-220.47) -78.74,-220.47 -78.74,-173.23 v1(-62.99,-157.48)
TPA0n_3: D10.3 J3.5 R112.2 U5.36 | length 649.8
  Top Layer w6: R112.2@-912,858.1 R112.2@-912,858 ; U5.36@-911.42,775 -911.42,809.28 cw(c-895.73,820) -912,829.82 R112.2@-912,858 ; R112.2@-910,860 R112.2@-912,858 ; R112.2@-910,872 v1@-880,872
  Top Layer w15: J3.5@-659.06,951.22 -655,955.28 D10.3@-655,1008
  MidLayer1 w6: v1(-880,876) cw(c-880,904) -880,932 -801,932 cw(c-801,922) -801,912 -840,912 ccw(c-840,902) -840,892 -718.28,892 J3.5@-659.06,951.22
TPA0p_3: D9.3 J3.6 R111.2 U5.37 | length 649.3
  Top Layer w6: U5.37@-931.1,775 -931.1,821.1 -940,830 -940,915 -935,920 R111.2@-910,920 ; R111.2@-910,908 v1@-880,908
  Top Layer w15: D9.3@-545,1008 -545,955.28 J3.6@-540.95,951.22
  MidLayer1 w6: v1(-880,904) -848,872 -710,872 -667,915 -577.17,915 J3.6@-540.95,951.22
TPA1n_3: D6.3 J4.5 R110.2 U5.45 | length 605.8
  Top Layer w6: R110.2@-1091.9,858.1 -1091.9,820 ccw(c-1072.9,820) -1088.58,809.28 U5.45@-1088.58,775 ; R110.2@-1090,872 v1@-1060,872
  Top Layer w15: J4.5@-1459.06,951.22 -1455,955.28 D6.3@-1455,1008
  MidLayer1 w6: J4.5@-1459.06,951.22 -1422.83,915 -1333,915 -1290,872 -1064,872 v1(-1060,876)
TPA1p_3: D5.3 J4.6 R109.2 U5.46 | length 606.4
  Top Layer w6: U5.46@-1108.27,775 -1108.27,818.27 -1120,830 -1120,915 -1115,920 R109.2@-1090,920 ; R109.2@-1090,908 v1@-1060,908
  Top Layer w15: D5.3@-1345,1008 -1345,955.28 J4.6@-1340.95,951.22
  MidLayer1 w6: J4.6@-1340.95,951.22 -1281.72,892 -1090,892 -1080,902 -1080,913 cw(c-1070,913) -1060,913 v1(-1060,904)
TPB0n_3: D12.3 J3.3 R113.1 U5.34 | length 609.1
  Top Layer w6: U5.34@-872.05,778.9 -872.05,816 v1(-868.05,820)
  Top Layer w10: J3.3@-674.89,850 ccw(c-659.06,872.48) J3.3@-659.06,844.98
  Top Layer w15: D12.3@-713,850 -674.89,850 -659.06,850 J3.3@-659.06,872.48
  MidLayer1 w6: v1(-868.05,820) -856.05,832 -781,832 cw(c-781,822) -781,812 -836,812 ccw(c-836,802) -836,792 -739.54,792 J3.3@-659.06,872.48
  Bottom Layer w6: v1(-868.05,820) -868.05,842.9 -860.95,850 R113.1@-840.95,850
TPB0p_3: D11.3 J3.4 R114.1 U5.35 | length 609.2
  Top Layer w6: v1(-895.73,820) -891.73,816 U5.35@-891.73,775
  Top Layer w10: J3.4@-540.94,844.98 ccw(c-540.94,872.48) J3.4@-525.11,850
  Top Layer w15: J3.4@-540.95,872.48 -540.94,850 -525.11,850 D11.3@-487,850
  MidLayer1 w6: v1(-895.73,820) -847.73,772 -731.26,772 -667,836.26 -577.17,836.26 J3.4@-540.95,872.48
  Bottom Layer w6: R114.1@-922.83,850 -902.83,850 -895.73,842.9 v1(-895.73,820)
TPB1n_3: D8.3 J4.3 R115.1 U5.43 | length 664.4
  Top Layer w6: U5.43@-1049.21,778.9 -1049.21,816 v1(-1045.21,820)
  Top Layer w10: J4.3@-1474.89,850 ccw(c-1459.06,872.48) J4.3@-1459.06,844.98
  Top Layer w15: D8.3@-1513,850 -1474.89,850 -1459.06,850 J4.3@-1459.06,872.48
  MidLayer1 w6: J4.3@-1459.06,872.48 -1422.83,836.26 -1333,836.26 -1268.74,772 -1093.21,772 v1(-1045.21,820)
  Bottom Layer w6: v1(-1045.21,820) -1045.21,842.9 -1038.11,850 R115.1@-1018.11,850
TPB1p_3: D7.3 J4.4 R116.1 U5.44 | length 666.1
  Top Layer w6: v1(-1072.9,820) -1068.9,816 U5.44@-1068.9,775
  Top Layer w10: J4.4@-1340.94,844.98 ccw(c-1340.94,872.48) J4.4@-1325.11,850
  Top Layer w15: J4.4@-1340.95,872.48 -1340.94,850 -1325.11,850 D7.3@-1287,850
  MidLayer1 w6: J4.4@-1340.95,872.48 -1260.46,792 -1105,792 ccw(c-1105,802) -1105,812 -1157,812 cw(c-1157,822) -1157,832 -1084.9,832 v1(-1072.9,820)
  Bottom Layer w6: R116.1@-1100,850 -1080,850 -1072.9,842.9 v1(-1072.9,820)
TxD1_6: J10.5 U1.B12 | length 874
  Top Layer w5: v1(-482,31.5) -450.5,62.99 -283.46,62.99 U1.B12@-267.72,47.24
  MidLayer 4 w5: J10.5@-865,-450 -800,-385 -800,-335 -525,-60 -525,-11.5 v1(-482,31.5)
V-FAULT_3: C41.1 D5.2 D6.2 D7.2 D8.2 D9.2 D10.2 D11.2 D12.2 Q6.2 R56.1 R57.2 R93.1 TP8.1 | length 1001.9
  Top Layer w12: R57.2@-1600,440 -1582.03,440 -1575,447.03 -1575,493 C41.1@-1577,495 -1575,497 R93.1@-1575,550 R56.1@-1575,585
  Top Layer w15: D8.2@-1567,830 v1(-1540,830) ; v1(-1475,1035) D6.2@-1475,1062 ; v1(-1365,1035) D5.2@-1365,1062 ; D7.2@-1233,870 -1212.22,870 -1205,862.78 v1(-1205,850) ; D12.2@-767,830 v1(-740,830) ; v1(-675,1035) D10.2@-675,1062 ; v1(-565,1035) D9.2@-565,1062 ; v1(-460,870) D11.2@-433,870
  Bottom Layer w12: TP8.1@800,0 800,295 785,310 785,345 810,370 v1(810,585)
  other v1: -1530,480 -1490,480 -1530,510 -1490,510
V-IN_10: C59.1 C60.1 C68.1 C69.1 L15.2 pad.0@1710,-1370 R102.1 U16.15 U16.16 U16.21 U16.22 | length 2007.6
  Top Layer w11: U16.22@871.1,-1198 871.1,-1180 ; C68.1@871.1,-970 871.1,-1180 ; U16.21@890.79,-1198 890.79,-1179.96 cw(c900.63,-1180) 900.63,-1170.16 913,-1170.16 C59.1@913,-1099.41 ; 890.79,-1180 ccw(c880.94,-1180) 871.1,-1180 ; 913.1,-1170.15 cw(c940,-1172.5) 966.9,-1170.15 ; C60.1@967,-1099.41 967,-1170.16 979.37,-1170.16 cw(c979.37,-1180) 989.21,-1179.96 ; U16.16@989.21,-1198 989.21,-1179.96 ; U16.15@1008.9,-1198 1008.9,-1179.94 ; 1008.9,-1180 ccw(c999.06,-1180) 1008.9,-1179.94 ; C69.1@1008.9,-970 1008.9,-1179.94 ; 989.21,-1179.96 cw(c999.06,-1180) 1008.9,-1179.94
  Top Layer w18: 1070,-910 v1(1095,-910) 1095,-885
  Top Layer w55: C69.1@960,-935 C69.1@960,-930 ; C69.1@987.5,-907.5 1047.5,-907.5 1100,-855 L15.2@1100,-800
  MidLayer1 w12: v1(1095,-910) 1095,-975 1200,-1080 1200,-1180 1280,-1260 1600,-1260 v1(1710,-1370)
  Bottom Layer w12: R102.1@1095,-940 v1(1095,-910)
